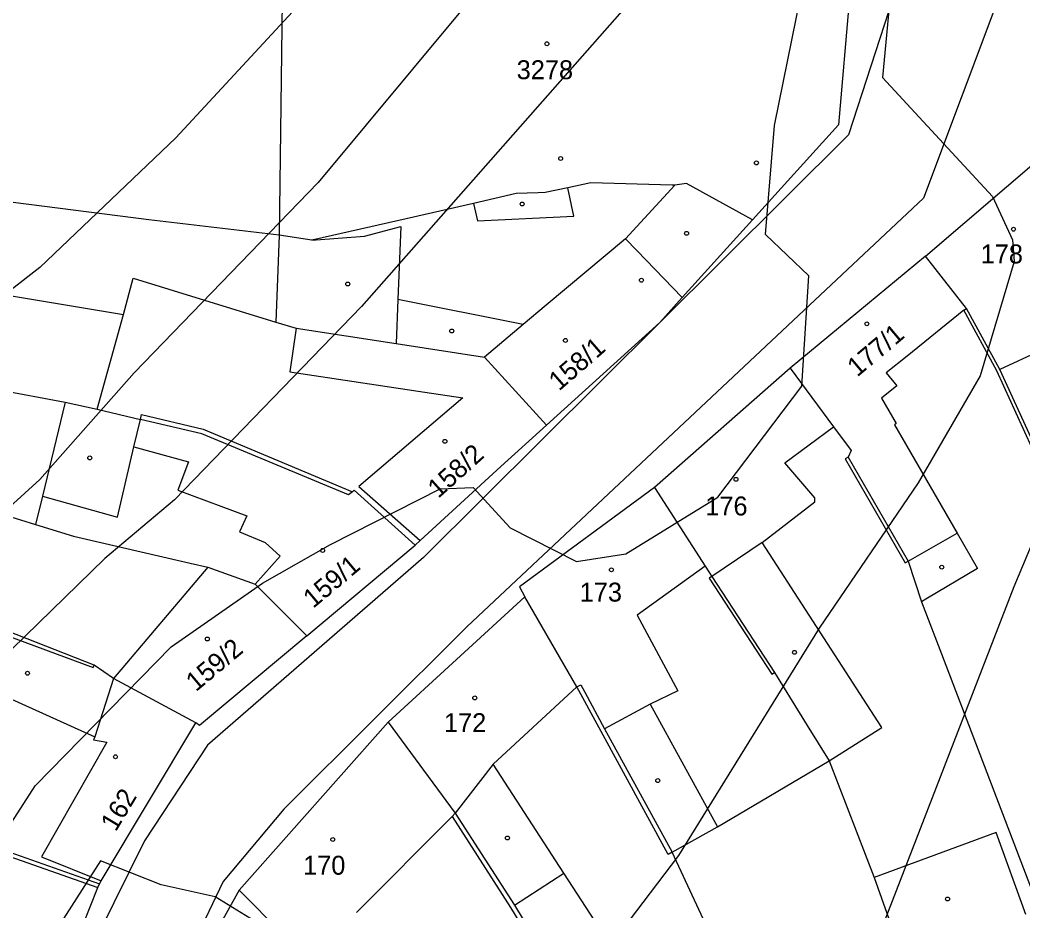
# Model space of a CAD drawing. Extents: x -555860 to -552701, y -1187050 to -1182291.
# Drawn here: x -554605.7 to -554515.8, y -1184662.8 to -1184582.9 of the extents above; entities that cross this region are included whole.
import ezdxf

# ---------------------------------------------------------------- set-up
doc = ezdxf.new("R2010")
doc.units = 0
for name, color, linetype in [('CYKLISTI_stav', 7, 'Continuous'), ('LEG_2b', 7, 'Continuous'), ('Level 25', 7, 'Continuous'), ('Level 40', 7, 'Continuous'), ('Level 41', 7, 'Continuous'), ('navrh_BV', 7, 'Continuous')]:
    doc.layers.add(name, color=color, linetype=linetype)

msp = doc.modelspace()

# ---------------------------------------------------------------- linework, layer by layer
at = {"layer": 'CYKLISTI_stav'}
for p, q in [((-554546.97, -1184597.74), (-554551.41, -1184602.55)), ((-554556.02, -1184600.52), (-554556.56, -1184597.98)), ((-554565.03, -1184599.37), (-554564.68, -1184600.93)), ((-554564.68, -1184600.93), (-554556.02, -1184600.52)), ((-554574.81, -1184602.32), (-554571.54, -1184601.44)), ((-554571.54, -1184601.44), (-554571.8, -1184607.99)), ((-554579.51, -1184602.68), (-554574.81, -1184602.32)), ((-554551.41, -1184602.55), (-554558.5, -1184608.5)), ((-554551.41, -1184602.55), (-554550.38, -1184603.61)), ((-554550.38, -1184603.61), (-554546.31, -1184607.82)), ((-554571.8, -1184607.99), (-554571.96, -1184611.94)), ((-554560.57, -1184610.24), (-554571.8, -1184607.99)), ((-554558.5, -1184608.5), (-554560.57, -1184610.24)), ((-554521.08, -1184608.94), (-554526.16, -1184613.06)), ((-554517.84, -1184614.25), (-554520.82, -1184608.8)), ((-554560.57, -1184610.24), (-554564.05, -1184613.16)), ((-554580.94, -1184610.56), (-554581.5, -1184614.46)), ((-554526.16, -1184613.06), (-554528.02, -1184614.57)), ((-554514.21, -1184612.6), (-554517.84, -1184614.25)), ((-554581.5, -1184614.46), (-554569.38, -1184616.28)), ((-554528.02, -1184614.57), (-554527.08, -1184615.73)), ((-554513.15, -1184624.54), (-554517.84, -1184614.25)), ((-554527.08, -1184615.73), (-554528.45, -1184616.83)), ((-554569.38, -1184616.28), (-554566, -1184616.79)), ((-554566, -1184616.79), (-554575.32, -1184624.75)), ((-554528.45, -1184616.83), (-554527.12, -1184619.09)), ((-554595.47, -1184621.18), (-554594.9, -1184618.74)), ((-554589.38, -1184620.03), (-554594.9, -1184618.74)), ((-554527.12, -1184619.09), (-554527.28, -1184619.21)), ((-554527.28, -1184619.21), (-554521.66, -1184628.93)), ((-554576.23, -1184625.51), (-554589.38, -1184620.03)), ((-554537.13, -1184622.64), (-554532.75, -1184619.4)), ((-554596.96, -1184627.5), (-554595.47, -1184621.18)), ((-554595.47, -1184621.18), (-554590.58, -1184622.53)), ((-554590.58, -1184622.53), (-554591.53, -1184625.07)), ((-554534.43, -1184625.76), (-554537.13, -1184622.64)), ((-554531.44, -1184622.12), (-554526.06, -1184631.45)), ((-554575.32, -1184624.75), (-554569.82, -1184629.59)), ((-554603.68, -1184625.61), (-554596.96, -1184627.5)), ((-554591.53, -1184625.07), (-554587.69, -1184626.51)), ((-554575.89, -1184625.22), (-554576.23, -1184625.51)), ((-554587.69, -1184626.51), (-554585.34, -1184627.39)), ((-554539.15, -1184629.76), (-554534.44, -1184626.11)), ((-554534.44, -1184626.11), (-554534.43, -1184625.76)), ((-554585.34, -1184627.39), (-554586, -1184628.81)), ((-554586, -1184628.81), (-554583.7, -1184629.77)), ((-554526.06, -1184631.45), (-554521.66, -1184628.93)), ((-554521.66, -1184628.93), (-554519.83, -1184632.09)), ((-554583.7, -1184629.77), (-554582.35, -1184630.98)), ((-554539.15, -1184629.76), (-554543.66, -1184632.81)), ((-554528.41, -1184646.36), (-554539.15, -1184629.76)), ((-554582.35, -1184630.98), (-554584.62, -1184633.51)), ((-554544.26, -1184631.89), (-554550.36, -1184636.27)), ((-554588.86, -1184631.98), (-554597.31, -1184641.97)), ((-554543.66, -1184632.81), (-554538.04, -1184641.42)), ((-554519.83, -1184632.09), (-554524.47, -1184634.86)), ((-554524.47, -1184634.86), (-554524.86, -1184635.09)), ((-554550.36, -1184636.27), (-554546.72, -1184643.06)), ((-554609.36, -1184642.49), (-554598.97, -1184647.18)), ((-554597.31, -1184641.97), (-554598.97, -1184647.18)), ((-554563.27, -1184649.65), (-554555.77, -1184642.7)), ((-554555.77, -1184642.7), (-554555.42, -1184642.51)), ((-554555.42, -1184642.51), (-554555.06, -1184643.17)), ((-554555.06, -1184643.17), (-554553.27, -1184646.47)), ((-554546.72, -1184643.06), (-554549.18, -1184644.25)), ((-554549.18, -1184644.25), (-554553.27, -1184646.47)), ((-554549.18, -1184644.25), (-554543.16, -1184655.26)), ((-554598.97, -1184647.18), (-554599.09, -1184647.45)), ((-554553.27, -1184646.47), (-554547.23, -1184657.53)), ((-554533.15, -1184649.33), (-554528.41, -1184646.36)), ((-554597.89, -1184647.67), (-554603.77, -1184657.95)), ((-554599.09, -1184647.45), (-554597.89, -1184647.67)), ((-554563.27, -1184649.65), (-554566.67, -1184654.04)), ((-554556.92, -1184659.4), (-554563.27, -1184649.65)), ((-554575.51, -1184662.92), (-554566.95, -1184654.32)), ((-554566.67, -1184654.04), (-554561.36, -1184662.28)), ((-554614.15, -1184655.27), (-554598.7, -1184660.7)), ((-554518.17, -1184655.77), (-554529.11, -1184659.79)), ((-554515.51, -1184663.1), (-554518.17, -1184655.77)), ((-554603.77, -1184657.95), (-554598.4, -1184660.08)), ((-554561.36, -1184662.28), (-554556.92, -1184659.4)), ((-554554.15, -1184663.67), (-554556.92, -1184659.4)), ((-554561.36, -1184662.28), (-554558.72, -1184666.59))]:
    msp.add_line(p, q, dxfattribs=at)
at = {"layer": 'Level 25'}
for centre in [(-554558.447, -1184585.069), (-554557.217, -1184595.349), (-554539.667, -1184595.749), (-554560.667, -1184599.429), (-554545.927, -1184602.059), (-554516.617, -1184601.689), (-554576.307, -1184606.599), (-554549.977, -1184606.259), (-554529.767, -1184610.169), (-554566.977, -1184610.809), (-554556.787, -1184611.659), (-554567.597, -1184620.699), (-554599.437, -1184622.189), (-554541.497, -1184624.109), (-554578.557, -1184630.479), (-554523.047, -1184631.979), (-554552.667, -1184632.219), (-554588.897, -1184638.419), (-554536.247, -1184639.609), (-554605.017, -1184641.489), (-554564.917, -1184643.699), (-554597.129, -1184648.972), (-554548.507, -1184651.109), (-554577.647, -1184656.389), (-554561.987, -1184656.249), (-554522.527, -1184661.719)]:
    msp.add_circle(centre, 0.175, dxfattribs=at)
at = {"layer": 'Level 40'}
for points in [[(-554525.435, -1184498.785), (-554532.09, -1184507.382), (-554542.226, -1184518.769), (-554542.573, -1184525.08), (-554557.88, -1184550.504), (-554560.823, -1184557.3), (-554562.434, -1184562.67), (-554570.498, -1184569.223), (-554579.755, -1184580.567), (-554591.713, -1184593.487), (-554603.914, -1184605.134), (-554626.377, -1184622.606)], [(-554601.618, -1184710.942), (-554599.027, -1184705.478), (-554597.349, -1184700.069), (-554593.566, -1184694.026), (-554588.735, -1184692.416), (-554578.541, -1184695.817), (-554570.221, -1184697.48), (-554561.902, -1184697.065), (-554556.91, -1184695.677), (-554547.897, -1184690.824), (-554544.153, -1184687.774), (-554537.498, -1184679.732), (-554528.901, -1184665.59), (-554516.56, -1184633.698), (-554503.527, -1184602.64), (-554500.615, -1184593.765), (-554495.338, -1184576.095), (-554498.29, -1184571.262), (-554488.275, -1184553.831), (-554477.893, -1184542.801), (-554474.941, -1184541.19), (-554469.841, -1184542.532), (-554465.816, -1184544.411), (-554458.838, -1184548.439)]]:
    msp.add_lwpolyline(points, dxfattribs=at)
at = {"layer": 'Level 41'}
for points in [[(-554492.296, -1184503.498), (-554505.191, -1184513.204), (-554512.286, -1184517.836), (-554512.659, -1184524.364), (-554518.363, -1184529.844), (-554524.464, -1184539.135), (-554538.548, -1184559.985), (-554539.621, -1184566.888), (-554549.284, -1184579.344), (-554575.074, -1184608.602), (-554591.851, -1184625.934), (-554598.091, -1184631.202), (-554607.659, -1184640.492)], [(-554511.153, -1184505.302), (-554515.313, -1184509.6), (-554522.912, -1184518.022), (-554523.471, -1184524.55), (-554524.88, -1184526.238), (-554538.884, -1184545.097), (-554550.356, -1184558.91), (-554551.43, -1184564.817), (-554557.742, -1184571.996), (-554578.956, -1184597.508), (-554595.456, -1184614.564), (-554603.915, -1184624.131), (-554620.415, -1184639.106)], [(-554527.544, -1184579.506), (-554528.349, -1184588.098), (-554518.502, -1184598.756), (-554516.699, -1184602.64), (-554516.561, -1184604.58), (-554519.611, -1184614.84), (-554525.157, -1184624.408), (-554534.031, -1184637.442), (-554546.649, -1184657.825), (-554551.086, -1184663.647), (-554557.049, -1184669.332), (-554564.952, -1184673.908), (-554567.725, -1184674.186), (-554573.272, -1184671.968), (-554575.767, -1184669.888), (-554578.537, -1184666.908), (-554584.71, -1184663.686), (-554588.199, -1184661.538), (-554593.029, -1184660.464), (-554598.468, -1184658.292), (-554604.838, -1184668.25), (-554608.906, -1184676.405)], [(-554610.154, -1184660.598), (-554604.331, -1184651.584), (-554592.129, -1184639.106), (-554583.948, -1184633.42), (-554577.847, -1184629.954), (-554568.006, -1184624.967), (-554565.072, -1184624.831), (-554561.744, -1184628.453), (-554555.801, -1184631.479), (-554551.364, -1184630.786), (-554543.11, -1184625.69), (-554535.595, -1184615.754), (-554534.955, -1184605.864), (-554538.843, -1184602.177), (-554538.053, -1184592.379), (-554535.695, -1184580.731)]]:
    msp.add_lwpolyline(points, dxfattribs=at)
at = {"layer": 'navrh_BV'}
for p, q in [((-554514.53, -1184541.36), (-554531.42, -1184593.24)), ((-554508.61, -1184556.1), (-554524.68, -1184598.92)), ((-554530.71, -1184573.92), (-554532.3, -1184592.32)), ((-554582.17, -1184581.21), (-554582.45, -1184602.22)), ((-554540.01, -1184600.84), (-554532.3, -1184592.32)), ((-554531.42, -1184593.24), (-554548.33, -1184610.06)), ((-554524.49, -1184604.09), (-554512.94, -1184594.19)), ((-554594.14, -1184600.85), (-554620.95, -1184597.43)), ((-554554.51, -1184597.54), (-554556.56, -1184597.98)), ((-554547.22, -1184597.73), (-554554.51, -1184597.54)), ((-554546.97, -1184597.74), (-554547.22, -1184597.73)), ((-554545.93, -1184597.6), (-554546.97, -1184597.74)), ((-554540.01, -1184600.84), (-554545.93, -1184597.6)), ((-554561.2, -1184598.49), (-554565.03, -1184599.37)), ((-554559.22, -1184598.43), (-554561.2, -1184598.49)), ((-554558.59, -1184598.41), (-554559.22, -1184598.43)), ((-554556.56, -1184597.98), (-554558.59, -1184598.41)), ((-554565.03, -1184599.37), (-554571.71, -1184600.91)), ((-554524.68, -1184598.92), (-554565.59, -1184637.29)), ((-554648.29, -1184600.71), (-554596.42, -1184609.34)), ((-554582.45, -1184602.22), (-554594.14, -1184600.85)), ((-554571.71, -1184600.91), (-554579.51, -1184602.68)), ((-554546.31, -1184607.82), (-554540.01, -1184600.84)), ((-554582.45, -1184602.22), (-554582.75, -1184610.02)), ((-554579.51, -1184602.68), (-554582.45, -1184602.22)), ((-554524.49, -1184604.09), (-554536.63, -1184614.15)), ((-554520.82, -1184608.8), (-554524.49, -1184604.09)), ((-554596.42, -1184609.34), (-554595.55, -1184606.09)), ((-554595.55, -1184606.09), (-554582.75, -1184610.02)), ((-554650.11, -1184608.11), (-554601.63, -1184617.18)), ((-554548.33, -1184610.06), (-554546.31, -1184607.82)), ((-554598.77, -1184617.82), (-554596.42, -1184609.34)), ((-554521.08, -1184608.94), (-554520.82, -1184608.8)), ((-554518.11, -1184614.38), (-554521.08, -1184608.94)), ((-554582.75, -1184610.02), (-554580.94, -1184610.56)), ((-554548.33, -1184610.06), (-554569.5, -1184631.1)), ((-554558.48, -1184619.25), (-554548.33, -1184610.06)), ((-554580.94, -1184610.56), (-554571.96, -1184611.94)), ((-554571.96, -1184611.94), (-554564.05, -1184613.16)), ((-554564.05, -1184613.16), (-554558.48, -1184619.25)), ((-554536.63, -1184614.15), (-554548.81, -1184624.84)), ((-554536.63, -1184614.15), (-554532.75, -1184619.4)), ((-554513.43, -1184624.66), (-554518.11, -1184614.38)), ((-554601.63, -1184617.18), (-554603.68, -1184625.61)), ((-554601.63, -1184617.18), (-554598.77, -1184617.82)), ((-554598.77, -1184617.82), (-554594.9, -1184618.74)), ((-554594.9, -1184618.74), (-554594.79, -1184618.3)), ((-554594.79, -1184618.3), (-554589.28, -1184619.6)), ((-554562.59, -1184622.97), (-554558.48, -1184619.25)), ((-554589.28, -1184619.6), (-554575.89, -1184625.22)), ((-554532.75, -1184619.4), (-554531.18, -1184621.52)), ((-554531.18, -1184621.52), (-554531.44, -1184622.12)), ((-554531.44, -1184622.12), (-554531.7, -1184622.27)), ((-554531.7, -1184622.27), (-554526.32, -1184631.6)), ((-554569.82, -1184629.59), (-554562.59, -1184622.97)), ((-554603.68, -1184625.61), (-554604.3, -1184628.14)), ((-554575.89, -1184625.22), (-554575.73, -1184625.09)), ((-554575.73, -1184625.09), (-554570.26, -1184630)), ((-554548.81, -1184624.84), (-554560.91, -1184633.73)), ((-554548.81, -1184624.84), (-554544.26, -1184631.89)), ((-554606.98, -1184627.31), (-554604.3, -1184628.14)), ((-554604.3, -1184628.14), (-554600.89, -1184629.19)), ((-554600.89, -1184629.19), (-554590.43, -1184631.62)), ((-554579.97, -1184638.12), (-554570.26, -1184630)), ((-554570.26, -1184630), (-554569.82, -1184629.59)), ((-554590.43, -1184631.62), (-554588.86, -1184631.98)), ((-554569.5, -1184631.1), (-554588.87, -1184647.93)), ((-554544.26, -1184631.89), (-554543.66, -1184632.81)), ((-554526.32, -1184631.6), (-554526.06, -1184631.45)), ((-554526.06, -1184631.45), (-554524.86, -1184635.09)), ((-554588.86, -1184631.98), (-554584.62, -1184633.51)), ((-554543.66, -1184632.81), (-554543.91, -1184632.97)), ((-554584.62, -1184633.51), (-554579.97, -1184638.12)), ((-554560.91, -1184633.73), (-554560.44, -1184634.63)), ((-554543.91, -1184632.97), (-554538.29, -1184641.58)), ((-554560.44, -1184634.63), (-554572.69, -1184645.88)), ((-554555.77, -1184642.7), (-554560.44, -1184634.63)), ((-554524.86, -1184635.09), (-554523.07, -1184639.76)), ((-554599.04, -1184640.77), (-554610.68, -1184636.19)), ((-554611.42, -1184636.45), (-554599.12, -1184640.97)), ((-554565.59, -1184637.29), (-554582.04, -1184653.66)), ((-554579.97, -1184638.12), (-554589.61, -1184646.18)), ((-554523.07, -1184639.76), (-554514.31, -1184662.66)), ((-554599.12, -1184640.97), (-554599.04, -1184640.77)), ((-554597.31, -1184641.97), (-554599.04, -1184640.77)), ((-554538.29, -1184641.58), (-554538.04, -1184641.42)), ((-554538.04, -1184641.42), (-554535.1, -1184646.18)), ((-554589.92, -1184645.93), (-554597.31, -1184641.97)), ((-554547.58, -1184657.72), (-554555.77, -1184642.7)), ((-554598.4, -1184660.08), (-554589.92, -1184645.93)), ((-554589.61, -1184646.18), (-554589.92, -1184645.93)), ((-554572.69, -1184645.88), (-554586.04, -1184660.92)), ((-554572.69, -1184645.88), (-554566.67, -1184654.04)), ((-554535.1, -1184646.18), (-554533.15, -1184649.33)), ((-554588.87, -1184647.93), (-554594.53, -1184656.5)), ((-554543.16, -1184655.26), (-554533.15, -1184649.33)), ((-554533.15, -1184649.33), (-554529.11, -1184659.79)), ((-554582.04, -1184653.66), (-554587.48, -1184660.15)), ((-554566.67, -1184654.04), (-554566.95, -1184654.32)), ((-554566.95, -1184654.32), (-554561.7, -1184662.49)), ((-554614.05, -1184654.93), (-554598.56, -1184660.35)), ((-554547.23, -1184657.53), (-554543.16, -1184655.26)), ((-554594.53, -1184656.5), (-554602.26, -1184672.17)), ((-554547.23, -1184657.53), (-554547.58, -1184657.72)), ((-554537.76, -1184677.68), (-554547.23, -1184657.53)), ((-554529.11, -1184659.79), (-554526.41, -1184667.3)), ((-554600.08, -1184664.15), (-554598.7, -1184660.7)), ((-554598.7, -1184660.7), (-554598.56, -1184660.35)), ((-554598.56, -1184660.35), (-554598.4, -1184660.08)), ((-554587.48, -1184660.15), (-554596.62, -1184679.24)), ((-554586.04, -1184660.92), (-554590.62, -1184669.11)), ((-554580.24, -1184666.74), (-554586.04, -1184660.92)), ((-554561.7, -1184662.49), (-554559.04, -1184666.86))]:
    msp.add_line(p, q, dxfattribs=at)

# ---------------------------------------------------------------- texts
at = {"layer": 'LEG_2b'}
for s, p in [('3278', (-554561.16, -1184588.245)), ('178', (-554519.56, -1184604.755)), ('176', (-554544.25, -1184627.345)), ('173', (-554555.51, -1184635.065)), ('172', (-554567.68, -1184646.765)), ('170', (-554580.31, -1184659.545))]:
    msp.add_text(s, height=1.7, dxfattribs=at).set_placement(p)
for s, rotation, p in [('177/1', 40, (-554530.626, -1184614.985)), ('158/1', 41, (-554557.361, -1184616.24)), ('158/2', 42, (-554568.185, -1184625.865)), ('159/1', 40, (-554579.406, -1184635.725)), ('159/2', 40, (-554589.916, -1184643.195)), ('162', 59, (-554597.105, -1184655.758))]:
    msp.add_text(s, height=1.7, rotation=rotation, dxfattribs=at).set_placement(p)

doc.saveas('drawing.dxf')
